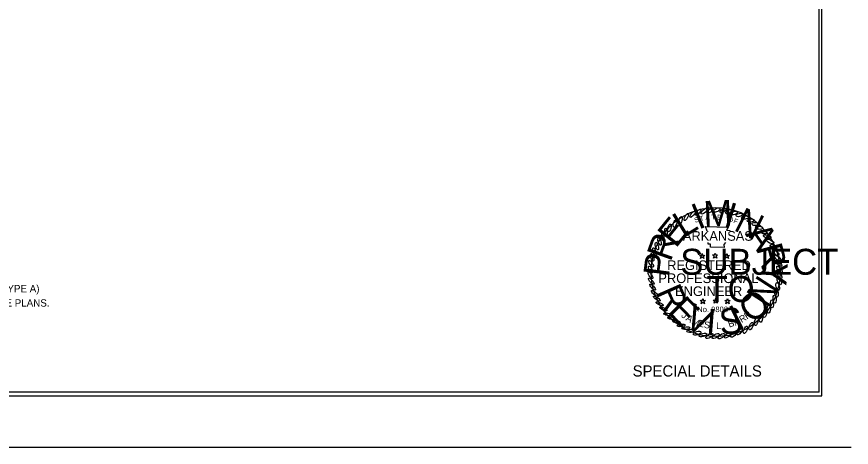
# Model space of a CAD drawing. Extents: x 714919 to 718439, y 1619644 to 1621844.
# Drawn here: x 717241 to 718439, y 1619644 to 1620261 of the extents above; entities that cross this region are included whole.
import ezdxf

# ---------------------------------------------------------------- set-up
doc = ezdxf.new("R2010")
doc.units = 0
for name, color, linetype in [('R_Border', 7, 'Continuous'), ('R_Border Notes', 7, 'Continuous'), ('R_Border PE', 7, 'Continuous'), ('R_Border Prem', 7, 'Continuous'), ('R_No Plot', 7, 'Continuous'), ('T_Notes', 7, 'Continuous')]:
    doc.layers.add(name, color=color, linetype=linetype)

msp = doc.modelspace()

# ---------------------------------------------------------------- linework, layer by layer
at = {"layer": 'R_Border'}
for p, q in [((718393, 1619722.6), (718392.9, 1621777.2)), ((718393, 1619722.6), (715231, 1619722.6)), ((714918.9, 1619643.7), (718439.1, 1619643.9))]:
    msp.add_line(p, q, dxfattribs=at)
at = {"layer": 'R_Border PE'}
for points in [[(718232, 1619953.9), (718229.9, 1619960.4), (718262.5, 1619959.5), (718260.1, 1619955.1), (718265.1, 1619954.8), (718264.8, 1619954.2)], [(718258.6, 1619937.6), (718255.9, 1619934.7), (718256.5, 1619930.2), (718237, 1619930.8), (718237, 1619935), (718233.5, 1619935), (718233.5, 1619937.6)]]:
    msp.add_lwpolyline(points, dxfattribs=at)
for points in [[(718225.2, 1619921.9), (718226.1, 1619919), (718229, 1619919), (718226.6, 1619917.5), (718227.5, 1619914.5), (718225.2, 1619916.3), (718222.8, 1619914.5), (718223.7, 1619917.5), (718221.3, 1619919), (718224.3, 1619919)], [(718243.5, 1619922.2), (718244.4, 1619919.6), (718247.1, 1619919.6), (718245, 1619917.8), (718245.9, 1619915.1), (718243.5, 1619916.6), (718241.1, 1619915.1), (718242, 1619917.8), (718239.7, 1619919.6), (718242.6, 1619919.6)], [(718260.4, 1619921.9), (718261.3, 1619919), (718264.2, 1619919), (718261.9, 1619917.5), (718262.8, 1619914.5), (718260.4, 1619916.3), (718258, 1619914.5), (718258.9, 1619917.5), (718256.5, 1619919), (718259.5, 1619919)], [(718226.1, 1619857.1), (718226.9, 1619854.1), (718229.9, 1619854.1), (718227.5, 1619852.7), (718228.4, 1619849.7), (718226.1, 1619851.5), (718223.7, 1619849.7), (718224.6, 1619852.7), (718222.2, 1619854.1), (718225.2, 1619854.1)], [(718244.4, 1619857.4), (718245.3, 1619854.7), (718248, 1619854.7), (718245.6, 1619853), (718246.8, 1619850.3), (718244.4, 1619851.8), (718242, 1619850.3), (718242.9, 1619853), (718240.6, 1619854.7), (718243.5, 1619854.7)], [(718261.3, 1619857.1), (718262.2, 1619854.1), (718265.1, 1619854.1), (718262.8, 1619852.7), (718263.6, 1619849.7), (718261.3, 1619851.5), (718258.9, 1619849.7), (718259.8, 1619852.7), (718257.4, 1619854.1), (718260.4, 1619854.1)]]:
    msp.add_lwpolyline(points, close=True, dxfattribs=at)
for centre, major_axis, ratio in [((718211.3, 1619978.1), (-3.58, -4.44), 0.329518), ((718219.4, 1619981), (-3.64, -4.4), 0.329518), ((718228.2, 1619982.8), (-4.59, -4.21), 0.348728), ((718236.5, 1619983.3), (-3.87, -3.02), 0.44237), ((718246.2, 1619984.2), (-4.21, -2.45), 0.475469), ((718254.9, 1619983.3), (-4.21, -2.45), 0.475469), ((718263, 1619981.8), (-4.21, -2.45), 0.475469), ((718271, 1619979.8), (-4.64, -1.48), 0.475469), ((718186, 1619964.7), (-1.53, -5.49), 0.394697), ((718193.9, 1619969.2), (-1.53, -5.49), 0.375751), ((718202.3, 1619974.1), (-2.46, -5.15), 0.329518), ((718278.4, 1619977), (-4.79, -0.89), 0.475469), ((718286.3, 1619973.4), (-4.85, -0.42), 0.475469), ((718294.6, 1619969.1), (-4.85, -0.42), 0.475469), ((718178.1, 1619958.4), (-1.53, -5.49), 0.391724), ((718301.2, 1619964), (-4.87, 0.11), 0.475469), ((718306.8, 1619958.7), (-5.09, 0.7), 0.451028), ((718168.2, 1619946.3), (0, -5.7), 0.322879), ((718172.9, 1619952.3), (0, -5.7), 0.322879), ((718313.1, 1619952.3), (-5.17, 1.18), 0.436264), ((718318.3, 1619946), (-5.3, 1.59), 0.418512), ((718160, 1619932.4), (1.57, -5.48), 0.322879), ((718163.8, 1619939.1), (1.57, -5.48), 0.322879), ((718322.6, 1619938.8), (-4.99, 2.77), 0.40589), ((718327.6, 1619930.9), (-4.66, 3.28), 0.40589), ((718156.5, 1619924.5), (1.57, -5.48), 0.322879), ((718330.7, 1619922.9), (-4.3, 3.75), 0.40589), ((718151.7, 1619907), (3.04, -4.83), 0.322879), ((718153.3, 1619916.4), (1.57, -5.48), 0.322879), ((718333.3, 1619915), (-4.3, 3.75), 0.40589), ((718335, 1619907.4), (-4.1, 3.96), 0.40589), ((718151.2, 1619898.9), (3.04, -4.83), 0.322879), ((718335.9, 1619899), (-3.5, 4.5), 0.40589), ((718150.7, 1619890.5), (3.04, -4.83), 0.322879), ((718152.1, 1619881.8), (3.92, -4.14), 0.322879), ((718335.6, 1619882.2), (-2.3, 5.22), 0.40589), ((718336.1, 1619890.8), (-2.77, 4.99), 0.40589), ((718154, 1619873.5), (3.92, -4.14), 0.322879), ((718333.5, 1619874.4), (-1.48, 5.51), 0.40589), ((718156.5, 1619864.7), (4.29, -3.76), 0.322879), ((718331.7, 1619864.9), (-1.02, 5.61), 0.40589), ((718159.9, 1619857.1), (4.67, -3.27), 0.322879), ((718164.1, 1619849.5), (5.13, -2.49), 0.322879), ((718325.2, 1619849.5), (-0.33, 5.69), 0.40589), ((718329, 1619856.3), (-0.33, 5.69), 0.40589), ((718169.4, 1619842.2), (5.13, -2.49), 0.322879), ((718315, 1619835.7), (0.91, 5.63), 0.40589), ((718320.7, 1619841.9), (0.27, 5.7), 0.40589), ((718175.4, 1619834.5), (5.58, -1.19), 0.322879), ((718181.1, 1619828.7), (5.58, -1.19), 0.322879), ((718302.6, 1619823.8), (1.36, 5.54), 0.40589), ((718309.5, 1619828.7), (0.91, 5.63), 0.40589), ((718188.1, 1619823.7), (5.58, -1.19), 0.322879), ((718194.9, 1619818.6), (5.68, 0.48), 0.322879), ((718201.6, 1619814.7), (5.68, 0.48), 0.322879), ((718278.8, 1619809.6), (3.39, 4.59), 0.40589), ((718287.2, 1619812.3), (2.43, 5.16), 0.40589), ((718295.2, 1619817.4), (2.26, 5.24), 0.40589), ((718208.8, 1619810.9), (5.68, 0.48), 0.40589), ((718217.8, 1619807.4), (5.5, 1.52), 0.40589), ((718226.1, 1619804.8), (5.5, 1.52), 0.40589), ((718235.3, 1619803.4), (4.91, 2.91), 0.40589), ((718244.5, 1619803.3), (4.91, 2.91), 0.40589), ((718252.6, 1619803.2), (4.63, 3.33), 0.40589), ((718261.7, 1619804.5), (4.36, 3.68), 0.40589), ((718270.1, 1619805.8), (4.08, 3.98), 0.40589)]:
    msp.add_ellipse(centre, major_axis=major_axis, ratio=ratio, dxfattribs=at)
at = {"layer": 'R_Border Prem'}
msp.add_circle((718244.3, 1619895), 92.6, dxfattribs=at)
at = {"layer": 'R_No Plot'}
msp.add_lwpolyline([(715227, 1619717.4), (718396.9, 1619717.5), (718397, 1621782.6), (715226.9, 1621782.4)], close=True, dxfattribs=at)

# ---------------------------------------------------------------- texts
at = {"layer": 'R_Border Notes'}
msp.add_text('SPECIAL DETAILS', height=16, rotation=359.9984, dxfattribs=at).set_placement((718125.2, 1619745.2))
at = {"layer": 'R_Border PE'}
for s, height, rotation, p in [('S', 6.91, 19.5814, (718215.1, 1619965.7)), ('T', 6.91, 14.9614, (718222.5, 1619968.1)), ('A', 6.91, 5.7216, (718229.9, 1619969.9)), ('T', 6.91, 1.1017, (718238.2, 1619970.5)), ('E', 6.91, 356.4818, (718246.2, 1619970.5)), ('O', 6.91, 342.6221, (718261.6, 1619968.4)), ('F', 6.91, 338.0022, (718269.3, 1619966)), ('ARKANSAS', 13.81, 360, (718197.3, 1619940)), ('REGISTERED', 13.81, 360, (718174.8, 1619898)), ('PROFESSIONAL', 13.814, 360, (718162.1, 1619879.3)), ('ENGINEER', 13.81, 360, (718186.1, 1619860.7)), ('No. 9808', 7.89, 360, (718217.9, 1619837.6)), ('J', 9.6, 322.4167, (718194.3, 1619831.3)), ('A', 9.6, 328.0171, (718200.8, 1619826.5)), ('M', 9.6, 333.6175, (718209.1, 1619821.7)), ('B', 9.6, 18.4207, (718263.9, 1619815.4)), ('A', 9.6, 24.0211, (718272.7, 1619818.1)), ('R', 9.6, 29.6215, (718281.5, 1619822.1)), ('R', 9.6, 35.2219, (718289.4, 1619826.9)), ('E', 9.6, 344.8183, (718218.6, 1619817.6)), ('S', 9.6, 350.4187, (718227, 1619815.2)), ('L', 9.6, 1.6195, (718245.3, 1619813.3)), ('.', 9.6, 7.2199, (718254.2, 1619813.9))]:
    msp.add_text(s, height=height, rotation=rotation, dxfattribs=at).set_placement(p)
at = {"layer": 'R_Border Prem'}
for s, height, rotation, p in [('M', 37.2, 2.6943, (718227.8, 1619959.7)), ('I', 37.2, 343.3781, (718254.1, 1619960.3)), ('I', 37.2, 22.0105, (718219.7, 1619955.6)), ('N', 37.2, 333.7199, (718268.7, 1619955.8)), ('E', 37.2, 50.9849, (718187.1, 1619928.4)), ('L', 37.2, 31.6686, (718198.1, 1619943.4)), ('A', 37.2, 304.7456, (718286.2, 1619949.2)), ('R', 37.2, 70.3011, (718179.7, 1619908.8)), ('R', 37.2, 285.4294, (718302.3, 1619930.4)), ('SUBJECT', 37.24, 360, (718193.6, 1619891.2)), ('P', 37.2, 82.6089, (718177.2, 1619887.1)), ('Y', 37.2, 266.1131, (718310.9, 1619910.4)), ('TO', 37.24, 360, (718231.2, 1619852.1)), ('N', 37.2, 57.1378, (718317.9, 1619842.5)), ('R', 37.2, 293.7639, (718157.9, 1619866.8)), ('O', 37.2, 36.5754, (718295.2, 1619820.3)), ('E', 37.2, 314.3262, (718173.9, 1619837.6)), ('V', 37.2, 334.8885, (718197, 1619817.3)), ('I', 37.2, 355.4508, (718229.8, 1619805.5)), ('S', 37.2, 5.732, (718251.3, 1619804.9)), ('I', 37.2, 26.2943, (718276.3, 1619810))]:
    msp.add_text(s, height=height, rotation=rotation, dxfattribs=at).set_placement(p)
at = {"layer": 'T_Notes'}
for s, p in [('7.  DRAINAGE OPENINGS TO BE CONSTRUCTED IN CONCRETE BARRIER WALL (SIDE TYPE A)', (716636.4, 1619866)), ("  AT EVERY 100' O.C. AND AT SAG LOCATIONS UNLESS OTHERWISE SPECIFIED ON THE PLANS.", (716636.4, 1619845.5))]:
    msp.add_text(s, height=10.5, dxfattribs=at).set_placement(p)

doc.saveas('drawing.dxf')
